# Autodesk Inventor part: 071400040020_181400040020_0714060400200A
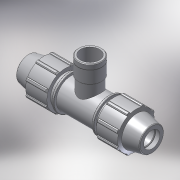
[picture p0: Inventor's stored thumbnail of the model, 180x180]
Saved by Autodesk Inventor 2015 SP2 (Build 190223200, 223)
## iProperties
Created: 2017-02
Part Number: 071400040020_181400040020_0714060400200A
Material: PVC-Piping
Description: PLASSON TEE WITH THREADED FEMALE OFFTAKE 40-2"-40
Document SubType Name: Modeling
Designer: KIM
Mass: 92.6774 g
Surface Area: 199.44 cm^2
Volume: 66.1981 cm^3
Density: 1.4 g/cm^3
Appearance: Smooth - White
Author: KIM
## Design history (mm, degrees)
derived "07140.ipt"
feature "Solid1::07140.ipt"
feature "Solid2::07140.ipt"
tag "TaggingFeature1"
body "Solid1"
other parameters: "d4" = 9.04167, "d5" = 26.04, "d7" = 82, "d11" = 3.61667, "d13" = 120 deg, "d15" = 12 deg, "d16" = 71.34, "d18" = 2, "d19" = 35 deg, "d20" = 17.5 deg, "d21" = 76.26, "d23" = 0, "d25" = 360 deg, "d27" = 1.64, "d33" = 0.8, "d42" = 39.06, "d43" = 2.46, "d46" = 1.2, "d68" = 6.51, "d72" = 78, "d76" = 56.656, "d80" = 1.69968, "d91" = 61.5, "d93" = 84, "d95" = 36, "d115" = 70.82, "d116" = 135 deg, "d117" = 65.1544, "d118" = 217, "d119" = 36, "d121" = 0, "d122" = 36, "d124" = 0, "d128" = 0, "d129" = 4, "d130" = 9, "d131" = 0.3, "d132" = 0.3, "d133" = 70.82, "E_" = 82, "A_" = 78, "l_" = 84, "Rp_" = 56.656, "H_" = 217
